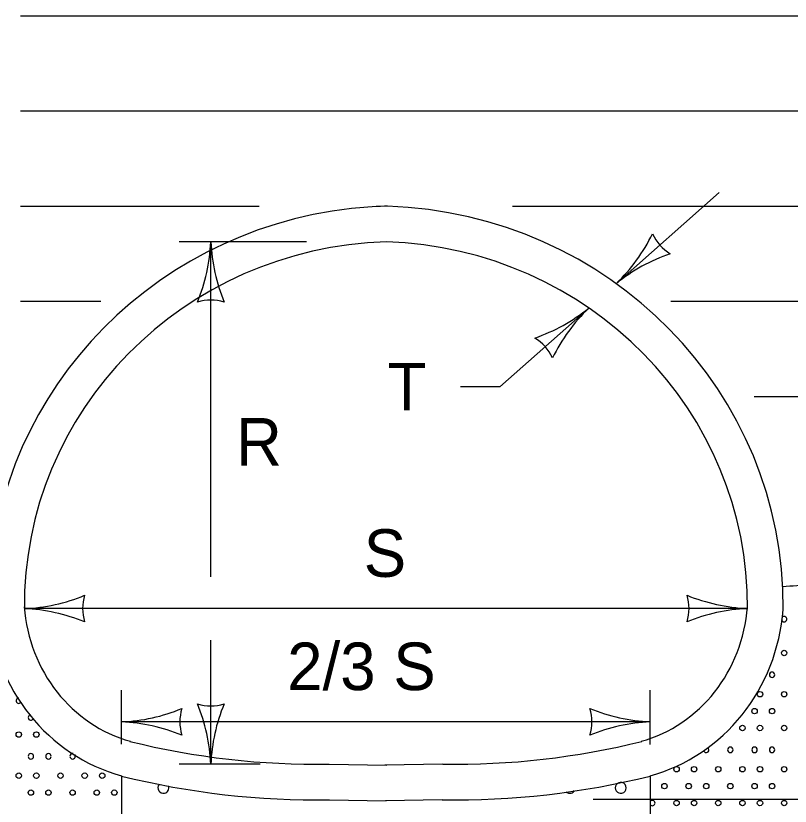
# Model space of a CAD drawing. Extents: x 49991.4 to 50021, y 49987.6 to 50011.4.
# Drawn here: x 50008.777 to 50009.754, y 49993.231 to 49994.228 of the extents above; entities that cross this region are included whole.
import ezdxf

# ---------------------------------------------------------------- set-up
doc = ezdxf.new("R2010")
doc.units = 0
for name, color, linetype in [('Level 1', 7, 'Continuous'), ('Level 2', 7, 'Continuous'), ('Level 3', 7, 'Continuous')]:
    doc.layers.add(name, color=color, linetype=linetype)

msp = doc.modelspace()

# ---------------------------------------------------------------- linework, layer by layer
at = {"layer": 'Level 1'}
for p, q in [((50008.7831, 49994.22779), (50010.75504, 49994.22779)), ((50008.7831, 49994.10779), (50010.5829, 49994.10779)), ((50008.7831, 49993.98779), (50009.08421, 49993.98779)), ((50009.24632, 49993.98779), (50009.24245, 49993.98779)), ((50009.40389, 49993.98779), (50010.42121, 49993.98779)), ((50008.7831, 49993.86779), (50008.88476, 49993.86779)), ((50009.60335, 49993.86779), (50010.2705, 49993.86779)), ((50009.70863, 49993.74779), (50010.1881, 49993.74779)), ((50009.17235, 49993.28419), (50009.24535, 49993.28273)), ((50009.31576, 49993.28419), (50009.24257, 49993.28273)), ((50008.91072, 49993.26941), (50008.91072, 49993.14749)), ((50009.57739, 49993.26926), (50009.57739, 49993.14418)), ((50009.17303, 49993.23919), (50009.24428, 49993.23775)), ((50009.31508, 49993.23919), (50009.24363, 49993.23775))]:
    msp.add_line(p, q, dxfattribs=at)
for centre in [(50009.74641, 49993.42436), (50009.71593, 49993.37243), (50009.74641, 49993.37243), (50009.70903, 49993.3511), (50009.73117, 49993.3511), (50009.69379, 49993.32976), (50009.71593, 49993.32976), (50009.74641, 49993.32976), (50008.78109, 49993.32157), (50008.80323, 49993.32157), (50009.61069, 49993.27783), (50009.63283, 49993.27783), (50009.66331, 49993.27783), (50009.69379, 49993.27783), (50009.71593, 49993.27783), (50009.74641, 49993.27783), (50008.78109, 49993.26965), (50008.80323, 49993.26965), (50008.83371, 49993.26965), (50008.86419, 49993.26965), (50008.88633, 49993.26965), (50009.59545, 49993.2565), (50009.59545, 49993.2565), (50009.62593, 49993.2565), (50009.64807, 49993.2565), (50009.67855, 49993.2565), (50009.67855, 49993.2565), (50009.70903, 49993.2565), (50009.73117, 49993.2565), (50008.79633, 49993.24831), (50008.81847, 49993.24831), (50008.84895, 49993.24831), (50008.84895, 49993.24831), (50008.87943, 49993.24831), (50008.90157, 49993.24831), (50009.61069, 49993.23516), (50009.63283, 49993.23516), (50009.66331, 49993.23516), (50009.69379, 49993.23516), (50009.71593, 49993.23516), (50009.74641, 49993.23516)]:
    msp.add_circle(centre, 0.00341, dxfattribs=at)
for centre, radius, start, end in [((50009.74641, 49993.46703), 0.00341, 188.7543, 153.61406), ((50009.73117, 49993.39693), 0.00341, 0, 180), ((50009.73117, 49993.39682), 0.00341, 180, 0), ((50008.78109, 49993.36425), 0.00341, 99.56823, 322.20503), ((50008.79633, 49993.34291), 0.00341, 99.39905, 341.38194), ((50009.64807, 49993.30222), 0.00341, 186.42629, 0), ((50009.64807, 49993.30233), 0.00341, 0, 59.42324), ((50009.67855, 49993.30233), 0.00341, 0, 180), ((50009.67855, 49993.30222), 0.00341, 180, 0), ((50009.67855, 49993.30222), 0.00341, 180, 0), ((50009.70903, 49993.30233), 0.00341, 0, 180), ((50009.70903, 49993.30222), 0.00341, 180, 0), ((50009.73117, 49993.30233), 0.00341, 0, 180), ((50009.73117, 49993.30222), 0.00341, 180, 0), ((50008.79633, 49993.29414), 0.00341, 0, 180), ((50008.79633, 49993.29403), 0.00341, 180, 0), ((50008.81847, 49993.29414), 0.00341, 0, 180), ((50008.81847, 49993.29403), 0.00341, 180, 0), ((50008.84895, 49993.29414), 0.00341, 80.64535, 180), ((50008.84895, 49993.29403), 0.00341, 180, 0), ((50008.84895, 49993.29403), 0.00341, 180, 0), ((50008.84895, 49993.29414), 0.00341, 0, 38.98587), ((50009.54027, 49993.25429), 0.00682, 77.07903, 282.92097), ((50009.54036, 49993.25429), 0.00682, 282.92097, 77.07903), ((50008.96337, 49993.25429), 0.00682, 140.49714, 282.92097), ((50008.96346, 49993.25429), 0.00682, 282.92097, 20.87741), ((50009.47617, 49993.25429), 0.00682, 226.02089, 282.92097), ((50009.47626, 49993.25429), 0.00682, 282.92097, 329.7915), ((50009.58021, 49993.23516), 0.00341, 214.20217, 145.79783)]:
    msp.add_arc(centre, radius, start, end, dxfattribs=at)
for centre, major_axis, ratio, start_param, end_param in [((50009.25853, 49993.48472), (-0.51524, -0.01494), 0.976362, 4.715363, 4.796646), ((50009.22958, 49993.48472), (0.51524, -0.01494), 0.976362, 0.018778, 1.566912), ((50009.25853, 49993.48472), (-0.51524, -0.01494), 0.976362, 4.796646, 6.264407), ((50009.25853, 49993.48472), (-0.47026, -0.01364), 0.9741, 4.713552, 6.264407), ((50009.22958, 49993.48472), (0.47026, -0.01364), 0.9741, 0.018778, 1.566912), ((50008.96776, 49993.49725), (0, -0.23546), 0.956933, 4.789023, 6.027407), ((50008.96776, 49993.49725), (0, -0.19046), 0.946758, 4.789023, 6.027407), ((50009.52035, 49993.49725), (0, -0.19046), 0.946758, 0.255726, 1.494162), ((50009.52035, 49993.49725), (0, -0.23546), 0.956933, 0.255726, 1.494162), ((50009.15699, 49994.35518), (0, -1.07111), 0.955124, 6.050475, 6.2982), ((50009.33112, 49994.35518), (0, -1.07111), 0.955124, 6.26817, 6.515885), ((50009.15699, 49994.35518), (0, -1.11611), 0.956933, 6.050475, 6.2982), ((50009.33112, 49994.35518), (0, -1.11611), 0.956933, 6.26817, 6.515885)]:
    msp.add_ellipse(centre, major_axis=major_axis, ratio=ratio, start_param=start_param, end_param=end_param, dxfattribs=at)
msp.add_spline([(50010.22682, 49993.51559), (50010.12914, 49993.50588), (50009.96544, 49993.51058), (50009.88224, 49993.50588), (50009.81574, 49993.51058), (50009.74446, 49993.50779)], degree=3, dxfattribs=at)
at = {"layer": 'Level 3'}
for p, q in [((50009.53462, 49993.89), (50009.66449, 49994.0049)), ((50009.14405, 49993.94276), (50008.98325, 49993.94276)), ((50009.02327, 49993.52036), (50009.02327, 49993.94276)), ((50009.38786, 49993.76015), (50009.49997, 49993.85934)), ((50009.38786, 49993.76015), (50009.33809, 49993.76015)), ((50009.74501, 49993.47922), (50009.74501, 49993.48882)), ((50009.70002, 49993.48036), (50008.78809, 49993.48036)), ((50009.02327, 49993.28408), (50009.02327, 49993.44036)), ((50008.91075, 49993.3092), (50008.91075, 49993.37754)), ((50009.57741, 49993.30915), (50009.57741, 49993.37754)), ((50009.57741, 49993.33754), (50008.91075, 49993.33754)), ((50009.08534, 49993.28408), (50008.98325, 49993.28408)), ((50010.43311, 49993.23943), (50009.50562, 49993.23943))]:
    msp.add_line(p, q, dxfattribs=at)
for centre, radius, start, end in [((50009.37181, 49994.05667), 0.233, 314.32797, 333.57782), ((50009.63065, 49993.97496), 0.05477, 203.63948, 239.36184), ((50008.80114, 49993.95192), 0.22232, 337.45601, 357.63952), ((50009.25598, 49993.95426), 0.233, 182.82731, 202.07716), ((50009.67495, 49993.71756), 0.22232, 108.95667, 129.14018), ((50009.02327, 49993.81455), 0.05477, 72.13882, 107.86118), ((50009.35964, 49994.03178), 0.22232, 288.95667, 309.14018), ((50009.66278, 49993.69267), 0.233, 134.32797, 153.57782), ((50009.40395, 49993.77439), 0.05477, 23.63948, 59.36184), ((50008.77893, 49993.70249), 0.22232, 272.36048, 292.54399), ((50008.91631, 49993.48036), 0.05477, 162.13882, 197.86118), ((50009.57174, 49993.48036), 0.05477, 342.13882, 17.86118), ((50009.71145, 49993.71307), 0.233, 247.92284, 267.17269), ((50008.7766, 49993.24765), 0.233, 67.92284, 87.17269), ((50009.70912, 49993.25823), 0.22232, 92.36048, 112.54399), ((50009.02327, 49993.4123), 0.05477, 252.13882, 287.86118), ((50008.79056, 49993.27259), 0.233, 2.82731, 22.07716), ((50009.24541, 49993.27493), 0.22232, 157.45601, 177.63952), ((50008.90159, 49993.55968), 0.22232, 272.36048, 292.54399), ((50009.03896, 49993.33754), 0.05477, 162.13882, 197.86118), ((50009.4492, 49993.33754), 0.05477, 342.13882, 17.86118), ((50009.58891, 49993.57026), 0.233, 247.92284, 267.17269), ((50008.89925, 49993.10483), 0.233, 67.92284, 87.17269), ((50009.58657, 49993.11541), 0.22232, 92.36048, 112.54399)]:
    msp.add_arc(centre, radius, start, end, dxfattribs=at)

# ---------------------------------------------------------------- texts
at = {"layer": 'Level 2'}
for s, p in [('T', (50009.24605, 49993.73015)), ('R', (50009.05505, 49993.66062)), ('S', (50009.21614, 49993.52036)), ('2/3 S', (50009.11959, 49993.37754))]:
    msp.add_text(s, height=0.06, dxfattribs=at).set_placement(p)

doc.saveas('drawing.dxf')
